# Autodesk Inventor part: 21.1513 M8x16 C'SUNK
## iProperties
Created: 2006-12
Part Number: 21.1513 M8x16 C'SUNK
Material: Steel, Mild
Description: Hexagon socket countersunk head cap screws
Document SubType Name: Modeling
Standard: DIN 7991
Designer: Andy Moles
Standards Organization: DIN
Language: en-US
Size Designation: M8x16
Categories: <MemberInstance Version="R10.0.0"><Categories><Category DisplayName="Fasteners" InternalName="e4da775c-781d-43d5-af7c-5136215cf5a6" Mnemonic="FSTN"><Category Di
Density: 7.86 g/cm^3
Author: Andy Moles
Revision Number: 1
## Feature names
1. Revolution1
2. Extrusion1
3. Fillet1
4. Chamfer1
